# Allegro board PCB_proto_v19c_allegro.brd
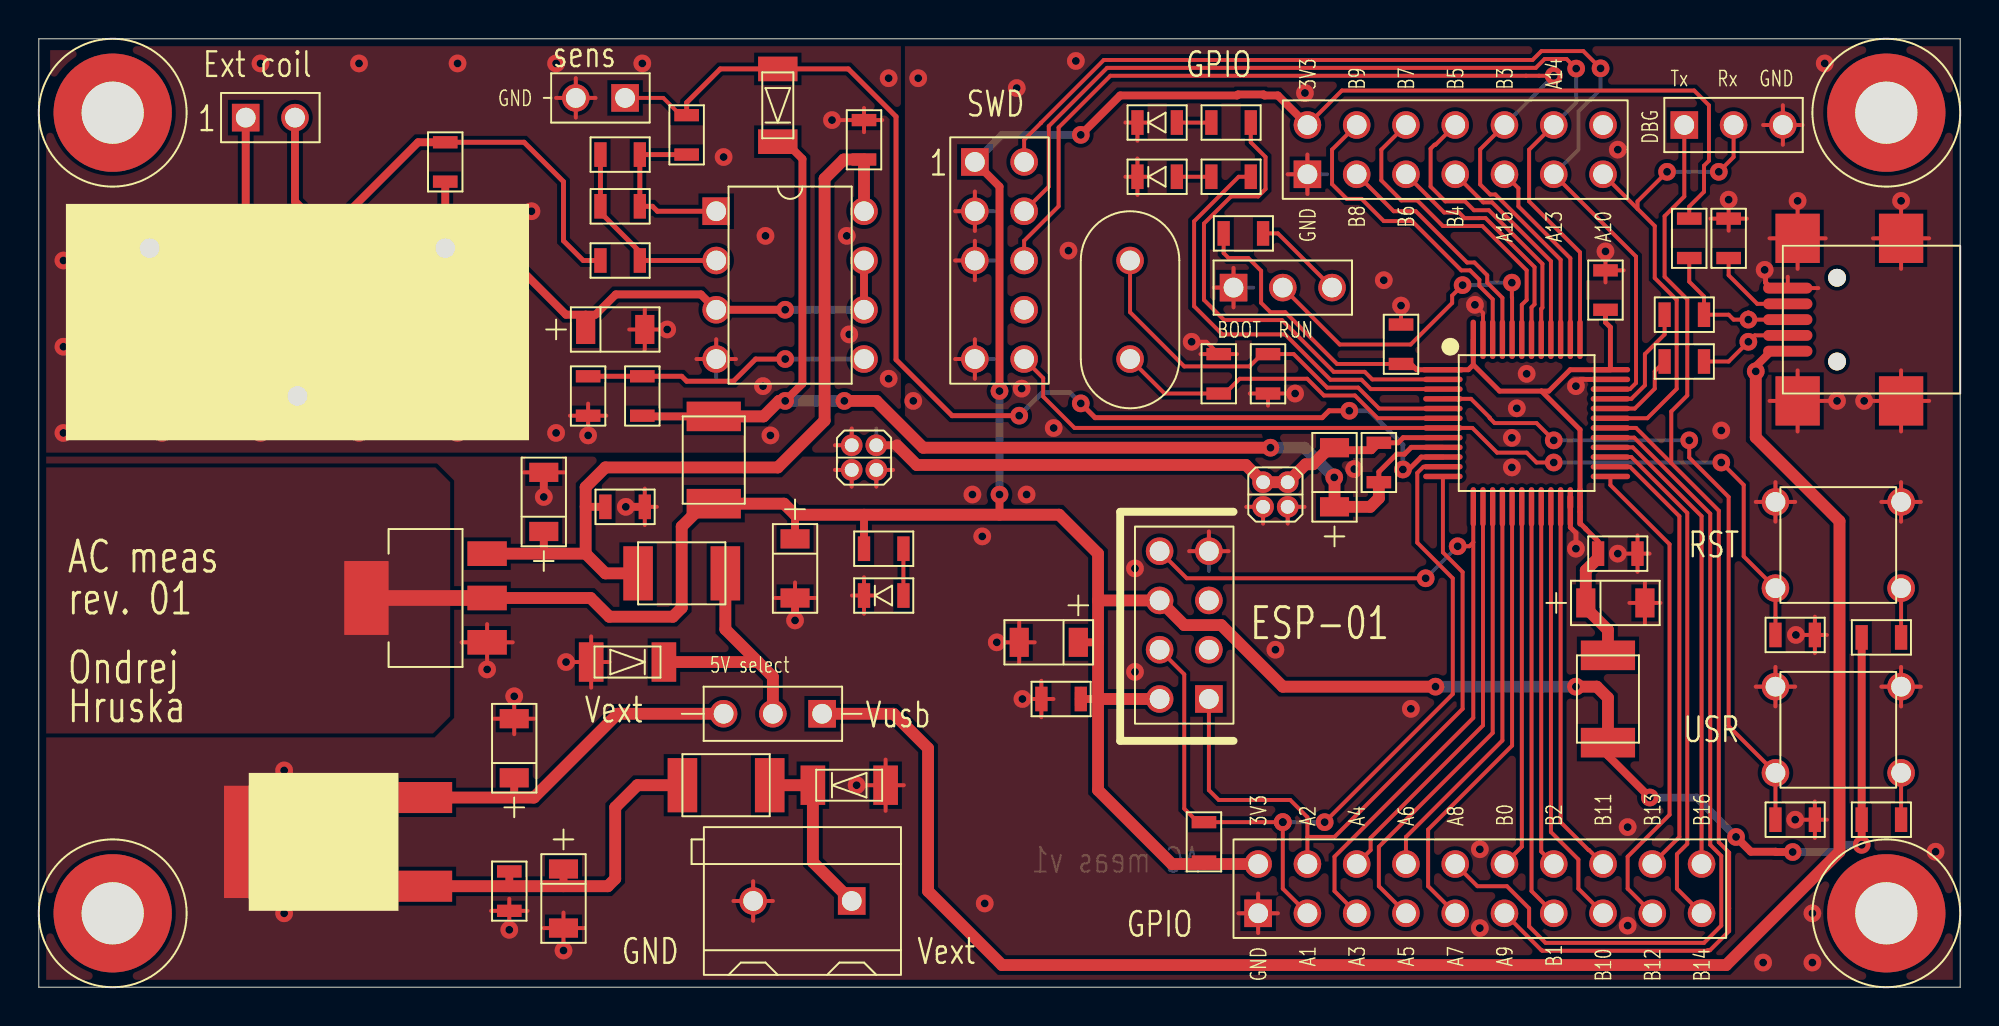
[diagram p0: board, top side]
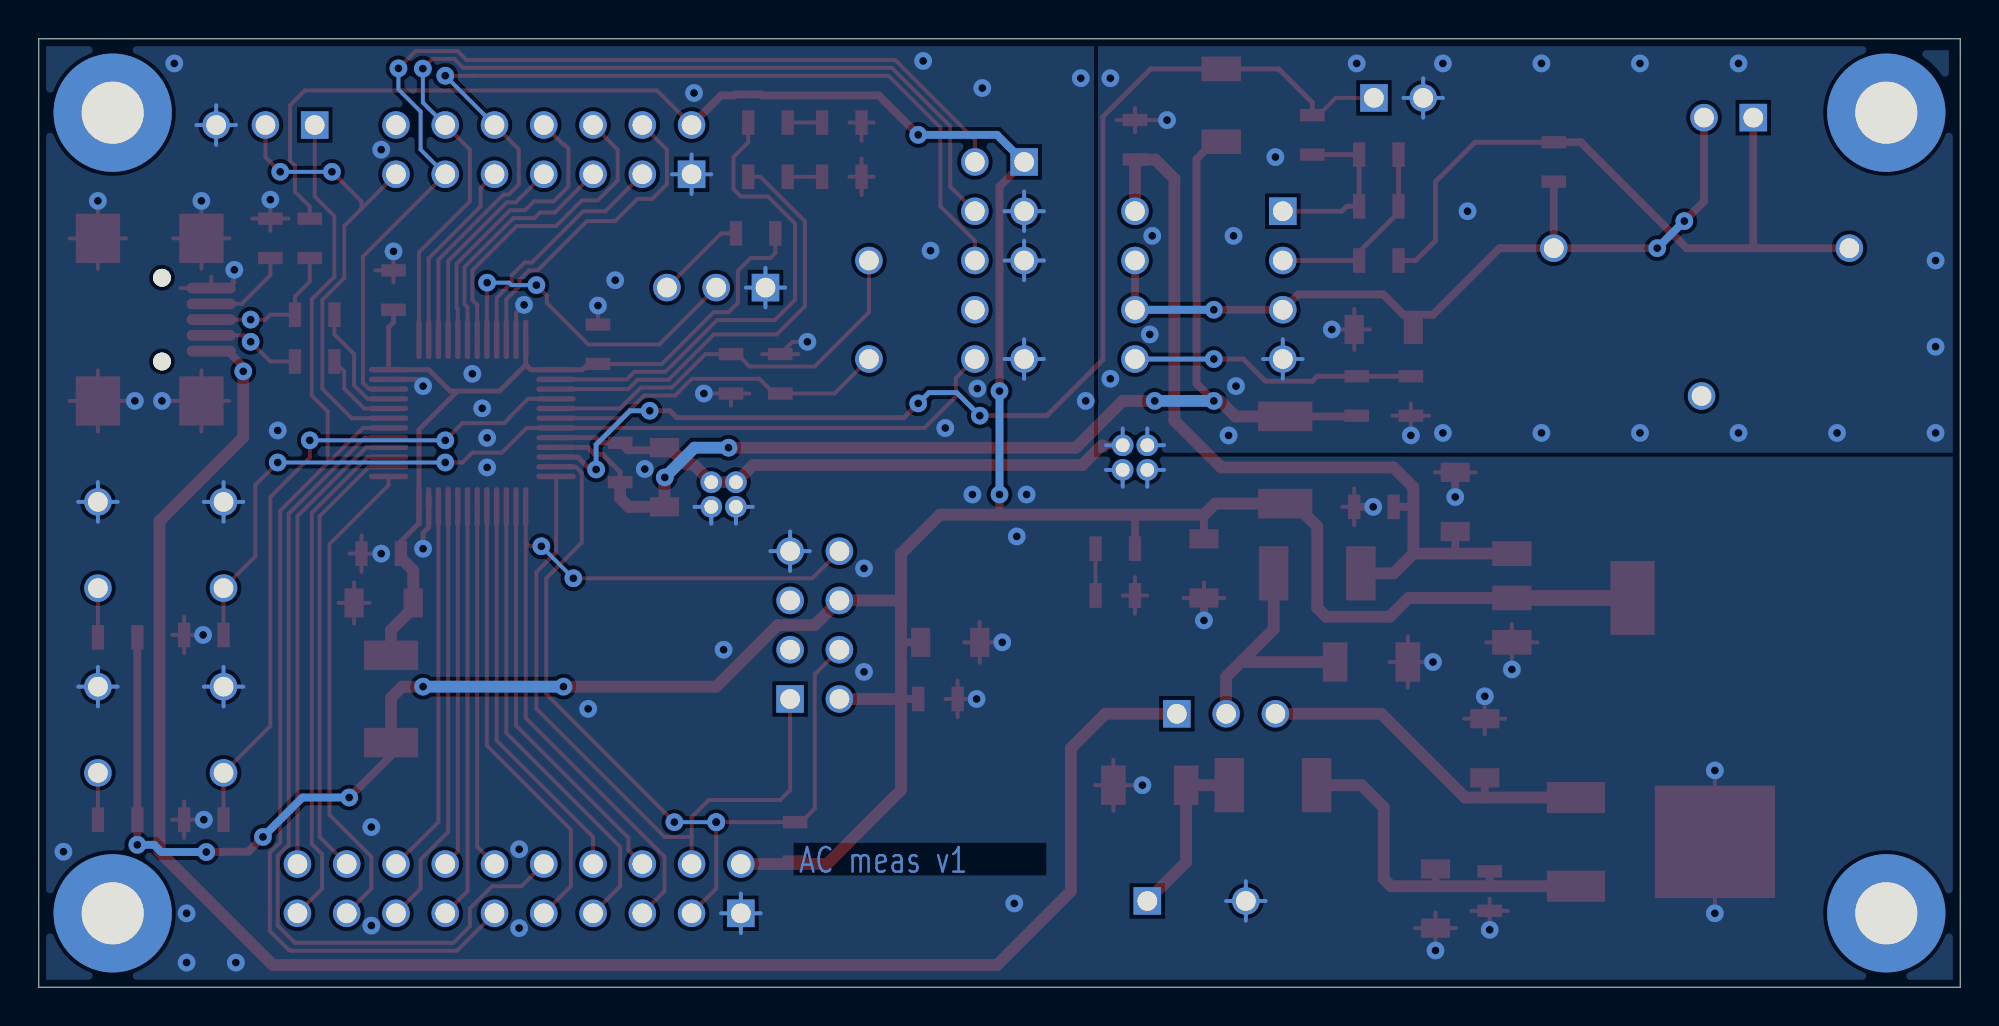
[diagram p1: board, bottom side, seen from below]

Outline 99.06 x 48.9 mm; copper layers: TOP, IN1, IN2, BOTTOM. Coordinates in mm from the lower left corner of the outline.
Outline path: 0,48.9 99.06,48.9 99.06,0 0,0 0,48.9

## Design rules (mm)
net group DP1: nets USB_DM USB_DP

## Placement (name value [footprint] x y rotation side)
C1  10u  [S_1206_CAP]  27.05 4.57 270 top
C2  10u  [S_1206_CAP]  24.51 12.32 90 top
C3  10u  [S_1206_CAP]  26.04 25.02 90 top
C4  100n  [S_0805]  30.23 24.77 0 top
C5  10u  [S_1206_CAP]  38.99 21.59 270 top
C6  1u  [S_1206_CAP]  66.8 26.29 90 top
C7  10n  [S_0805]  69.09 27.05 90 top
C8  10u  [S_1206_CAP]  81.28 19.81 0 top
C9  100n  [S_0805]  80.77 35.94 90 top
C10  100n  [S_0805]  70.23 33.15 90 top
C11  100n  [S_0805]  81.41 22.35 0 top
C12  100n  [S_0805]  90.55 18.16 0 top
C13  100n  [S_0805]  90.55 8.64 0 top
C14  1n5  [S_0805]  29.97 40.26 0 top
C15  10n  [S_0805]  42.55 43.69 90 top
C16  22u  [S_1206_CAP]  29.72 33.91 0 top
C17  22p  [S_0805]  63.37 31.62 270 top
C18  22p  [S_0805]  60.83 31.62 90 top
C19  100n  [S_0805]  24.26 4.95 270 top
C20  100n  [S_0805]  52.7 14.86 180 top
C21  10u  [S_1206_CAP]  52.07 17.78 180 top
D1  BAT42  [S_MINIMELF]  41.78 10.41 0 top
D2  BAT42  [S_MINIMELF]  30.35 16.76 180 top
D3  BAT42  [S_MINIMELF]  38.1 45.47 90 top
H1  MOUNT HOLE M3  [MOUNT_HOLE_M3]  3.81 45.09 0 top
H2  MOUNT HOLE M3  [MOUNT_HOLE_M3]  95.25 45.09 0 top
H3  MOUNT HOLE M3  [MOUNT_HOLE_M3]  95.25 3.81 0 top
H4  MOUNT HOLE M3  [MOUNT_HOLE_M3]  3.81 3.81 0 top
J1  V_EXT  [T_POWER_CON]  39.37 4.45 180 top
J2  PWR_SELECT  [T_SIP3]  37.85 14.1 270 top
J3  EXT_COIL  [T_SIP2]  10.67 44.83 90 top
J4  USB  [S_USB_MINI_B]  92.71 34.42 90 top
J6  SWD 5x2  [T_HEADER_SWD]  49.53 37.47 0 top
J7  GPIO1  [T_HEADER10X2]  74.3 5.08 90 top
J8  HEADER 7X2  [T_HEADER7X2]  73.03 43.18 90 top
J9  TEST_ANALOG_IN  [T_SIP2]  30.23 45.85 270 top
J10  DEBUG  [T_SIP3]  87.38 44.45 90 top
J11  ESP8266  [T_HEADER4X2]  59.05 18.67 180 top
J12  BOOT  [T_SIP3]  64.14 36.07 90 top
L1  27uH  [S_1210]  35.43 10.41 180 top
L2  27uH  [S_1210]  33.15 21.34 180 top
L3  27uH  [S_1210]  34.8 27.18 90 top
L4  27uH  [S_1210]  80.9 14.86 90 top
LD1  D1  [S_0805_LED]  57.66 44.58 0 top
LD2  D2  [S_0805_LED]  57.66 41.78 0 top
LD3  POWER  [S_0805_LED]  43.56 20.19 0 top
NOREF  -  []  99.06 0 90 top
NOREF#2  -  []  0 48.9 0 top
R1  100k  [S_0805]  95 18.03 0 top
R2  100k  [S_0805]  95 8.64 0 top
R3  150  [S_0805]  61.47 44.58 180 top
R4  150  [S_0805]  61.47 41.78 180 top
R5  150  [S_0805]  43.56 22.61 0 top
R6  1K  [S_0805]  20.95 42.55 270 top
R7  10k  [S_0805]  29.97 37.47 0 top
R8  20k  [S_0805]  29.97 42.93 0 top
R9  470R  [S_0805]  33.4 43.94 90 top
R10  1K  [S_0805]  31.11 30.48 90 top
R11  1K  [S_0805]  28.32 30.48 270 top
R12  1K  [S_0805]  85.09 38.61 90 top
R13  22  [S_0805]  84.84 32.26 180 top
R14  22  [S_0805]  84.84 34.67 180 top
R15  100k  [S_0805]  87.12 38.61 90 top
R18  10k  [S_0805]  62.1 38.86 180 top
R19  10k  [S_0805]  60.07 7.49 270 top
SB1  AGND BRIDGE  [T_AGND_BRIDGE]  42.55 27.3 270 top
SB2  AGND BRIDGE  [T_AGND_BRIDGE]  63.75 25.4 270 top
SW1  RESET  [T_BUTTON_KSM]  92.84 22.86 0 top
SW2  USER  [T_BUTTON_KSM]  92.84 13.34 0 top
TR1  AC-1010  [T_TALEMA_CUR_TR]  13.34 34.29 0 top
U1  LF50CDT-TR  [S_DPAK]  19.81 7.49 180 top
U2  LD1117AS33TR  [S_SOT223]  23.11 20.07 180 top
U3  OP213  [T_DIP8]  38.73 36.2 0 top
U4  STM32F303CC  [S_LQFP48]  76.71 29.08 0 top
X1  8MHz  [T_XTAL50]  56.26 34.92 270 top

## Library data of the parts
C1-C3 C5 C6 C8 C16 C21 = CAP POL
C4 C7 C9-C15 C17-C20 = CAPACITOR NON-POL
D1-D3 = DIODE
H1-H4 = MOUNT HOLE M3
J1 J3 J9 = HEADER 2
J2 J10 J12 = JUMPER 3
J4 = USB MINI
J6 = SWD 5x2
J7 = HEADER 10X2
J8 = HEADER 7X2
J11 = HEADER 4X2
L1-L4 = INDUCTOR
LD1-LD3 = LED
R1-R15 R18 R19 = RESISTOR
SB1 SB2 = AGND BRIDGE
SW1 SW2 = SW PUSHBUTTON-SPST-2
TR1 = ac-1010
U1 = LF50CDT-TR
U2 = LD1117AS33TR
U3 = OP213
U4 = stm32f303cct6
X1 = CRYSTAL

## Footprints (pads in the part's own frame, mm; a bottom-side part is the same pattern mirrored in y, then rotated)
MOUNT_HOLE_M3
  round 6.096 hole 3.2: 1(0,0)
S_0805
  rect 0.635x1.27 smd: 1(-1.016,0) 2(1.016,0)
S_0805_LED
  rect 0.635x1.27 smd: 1(-1.016,0) 2(1.016,0)
S_1206_CAP
  rect 0.991x1.499 smd: 1(-1.524,0) 2(1.524,0)
S_1210
  rect 1.524x2.794 smd: 1(-2.25,0) 2(2.25,0)
S_DPAK
  rect 2.997x1.6 smd: 1(0,2.286) 2(0,-2.286)
  rect 6.198x5.791 smd: 3(7.163,0)
S_LQFP48
  rect 2.032x0.279 smd: 1(-4.318,2.752)
  oval 2.032x0.279 smd: 2(-4.318,2.252) 3(-4.318,1.751) 4(-4.318,1.251) 5(-4.318,0.751) 6(-4.318,0.25) 7(-4.318,-0.25) 8(-4.318,-0.751) 9(-4.318,-1.251) 10(-4.318,-1.751) 11(-4.318,-2.252) 12(-4.318,-2.752) 25(4.318,-2.752) 26(4.318,-2.252) 27(4.318,-1.751) 28(4.318,-1.251) 29(4.318,-0.751) 30(4.318,-0.25) 31(4.318,0.25) 32(4.318,0.751) 33(4.318,1.251) 34(4.318,1.751) 35(4.318,2.252) 36(4.318,2.752)
  oval 0.279x2.032 smd: 13(-2.752,-4.318) 14(-2.252,-4.318) 15(-1.751,-4.318) 16(-1.251,-4.318) 17(-0.751,-4.318) 18(-0.25,-4.318) 19(0.25,-4.318) 20(0.751,-4.318) 21(1.251,-4.318) 22(1.751,-4.318) 23(2.252,-4.318) 24(2.752,-4.318) 37(2.752,4.318) 38(2.252,4.318) 39(1.751,4.318) 40(1.251,4.318) 41(0.751,4.318) 42(0.25,4.318) 43(-0.25,4.318) 44(-0.751,4.318) 45(-1.251,4.318) 46(-1.751,4.318) 47(-2.252,4.318) 48(-2.752,4.318)
S_MINIMELF
  rect 1.27x2.032 smd: 1(-1.875,0) 2(1.875,0)
S_SOT223
  rect 2.032x1.27 smd: 1(0,2.286) 2(0,0) 3(0,-2.286)
  rect 2.286x3.81 smd: 4(6.223,0)
S_USB_MINI_B
  round 0.914 hole 0.914: (-2.159,0) (2.159,0)
  oval 0.559x2.54 smd: 1(-1.626,2.54) 2(-0.813,2.54) 3(0,2.54) 4(0.813,2.54) 5(1.626,2.54)
  rect 2.54x2.286 smd: X1(-4.191,2.032) X2(4.191,2.032) X3(-4.191,-3.302) X4(4.191,-3.302)
T_AGND_BRIDGE
  round 1.118 hole 0.711: 1(-0.635,0.635) 2(0.635,0.635) 3(-0.635,-0.635) 4(0.635,-0.635)
T_BUTTON_KSM
  round 1.422 hole 1.016: 1(-3.302,2.159) 2(3.175,2.159) 3(3.175,-2.286) 4(-3.302,-2.286)
T_DIP8
  rect 1.422x1.422 hole 1.016: 1(-3.81,3.81)
  round 1.422 hole 1.016: 2(-3.81,1.27) 3(-3.81,-1.27) 4(-3.81,-3.81) 5(3.81,-3.81) 6(3.81,-1.27) 7(3.81,1.27) 8(3.81,3.81)
T_HEADER4X2
  rect 1.422x1.422 hole 1.016: 1(-1.27,3.81)
  round 1.422 hole 1.016: 2(1.27,3.81) 3(-1.27,1.27) 4(1.27,1.27) 5(-1.27,-1.27) 6(1.27,-1.27) 7(-1.27,-3.81) 8(1.27,-3.81)
T_HEADER7X2
  rect 1.422x1.422 hole 1.016: 1(-1.27,7.62)
  round 1.422 hole 1.016: 2(1.27,7.62) 3(-1.27,5.08) 4(1.27,5.08) 5(-1.27,2.54) 6(1.27,2.54) 7(-1.27,0) 8(1.27,0) 9(-1.27,-2.54) 10(1.27,-2.54) 11(-1.27,-5.08) 12(1.27,-5.08) 13(-1.27,-7.62) 14(1.27,-7.62)
T_HEADER10X2
  rect 1.422x1.422 hole 1.016: 1(-1.27,11.43)
  round 1.422 hole 1.016: 2(1.27,11.43) 3(-1.27,8.89) 4(1.27,8.89) 5(-1.27,6.35) 6(1.27,6.35) 7(-1.27,3.81) 8(1.27,3.81) 9(-1.27,1.27) 10(1.27,1.27) 11(-1.27,-1.27) 12(1.27,-1.27) 13(-1.27,-3.81) 14(1.27,-3.81) 15(-1.27,-6.35) 16(1.27,-6.35) 17(-1.27,-8.89) 18(1.27,-8.89) 19(-1.27,-11.43) 20(1.27,-11.43)
T_HEADER_SWD
  rect 1.422x1.422 hole 1.016: 1(-1.27,5.08)
  round 1.422 hole 1.016: 2(1.27,5.08) 3(-1.27,2.54) 4(1.27,2.54) 5(-1.27,0) 6(1.27,0) 8(1.27,-2.54) 9(-1.27,-5.08) 10(1.27,-5.08)
T_POWER_CON
  rect 1.422x1.422 hole 1.016: 1(-2.54,0)
  round 1.422 hole 1.016: 2(2.54,0)
T_SIP2
  rect 1.422x1.422 hole 1.016: 1(0,0)
  round 1.422 hole 1.016: 2(0,-2.54)
T_SIP3
  rect 1.422x1.422 hole 1.016: 1(0,2.54)
  round 1.422 hole 1.016: 2(0,0) 3(0,-2.54)
T_TALEMA_CUR_TR
  round 1.422 hole 1.016: 1(-7.62,3.81) 2(7.62,3.81) X1(0,-3.81)
T_XTAL50
  round 1.422 hole 1.016: 1(-2.54,0) 2(2.54,0)

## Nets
3V3: C5.1 C20.1 C21.1 J6.1(VCC) J7.2 J8.2 J11.2 J11.6 L3.1 L4.1 R1.1 R2.1 R5.1 R12.2 R19.2 U2.2(VOUT) U2.4(TAB_VOUT)
3V3_ANALOG: C6.1 C7.1 D3.1(K) L3.2 R10.1 U4.9(VDDA)
3V3_MCU: C8.1 C9.1 C10.1 C11.1 L4.2 R18.2 U4.1(VBAT) U4.24(VDD#24) U4.36(VDD#36) U4.48(VDD#48)
5V: C3.1 C4.1 C15.1 L2.2 U2.3(VIN) U3.8(VCC)
5V_REG_OUT: C2.1 J2.3(P3) U1.2(VOUT)
5V_USB: J2.1(P1) J4.1(VBUS)
GND: C1.2 C2.2 C3.2 C4.2 C5.2 C8.2 C9.2 C10.2 C11.2 C12.2 C13.2 C17.2 C18.2 C19.2 C20.2 C21.2 D1.2(A) D2.2(A) J1.2 J4.5(GND) J4.X1 J4.X2 J4.X3 J4.X4 J6.3(GND1) J6.5(GND2) J6.9(GNDD) J7.1 J8.1 J10.3(P3) J11.7 J12.1(P1) LD1.1(CATHODE) LD2.1(CATHODE) LD3.1(CATHODE) R15.2 SB1.2(B1) SB1.4(B2) SB2.2(B1) SB2.4(B2) SW1.1 SW1.2 SW2.1 SW2.2 U1.3(GND) U2.1(GND) U4.23(VSS#23) U4.35(VSS#35) U4.47(VSS#47)
GNDA: C6.2 C7.2 C15.2 C16.2 J9.2 R11.2 SB1.1(A1) SB1.3(A2) SB2.1(A1) SB2.3(A2) U3.4(GND) U4.8(VSSA)
ADC_IN: D3.2(A) J9.1 R9.2 U4.10(PA0)
ESP_NRST: J7.3 J11.4 R19.1 U4.11(PA1)
ESP_RX: J7.4 J11.1 U4.12(PA2)
ESP_TX: J7.5 J11.8 U4.13(PA3)
LED1: R3.1 U4.2(PC13)
LED2: R4.1 U4.3(PC14/OSC32_IN)
NRST: C12.1 J6.10(NRST) SW1.4 U4.7(NRST)
PA4: J7.6 U4.14(PA4)
PA5: J7.7 U4.15(PA5)
PA6: J7.8 U4.16(PA6)
PA7: J7.9 U4.17(PA7)
PA8: J7.10 U4.29(PA8)
PA9: J7.11 J10.1(P1) U4.30(PA9)
PA10: J8.13 J10.2(P2) U4.31(PA10)
PA13: J6.2(SWDIO) J8.11 U4.34(PA13)
PA14: J6.4(SWCLK) J8.12 U4.37(PA14)
PA15: J8.9 U4.38(PA15)
PB0: J7.12 U4.18(PB0)
PB1: J7.13 U4.19(PB1)
PB2: J7.14 U4.20(PB2)
PB3: J6.6(SWO) J8.10 U4.39(PB3)
PB4: J8.7 U4.40(PB4)
PB5: J8.8 U4.41(PB5)
PB6: J8.5 U4.42(PB6)
PB7: J8.6 U4.43(PB7)
PB8: J8.3 U4.45(PB8)
PB9: J8.4 U4.46(PB9)
PB10: J7.15 U4.21(PB10)
PB11: J7.16 U4.22(PB11)
PB12: J7.17 U4.25(PB12)
PB13: J7.18 U4.26(PB13)
PB14: J7.19 U4.27(PB14)
PB15: J7.20 U4.28(PB15)
USB_DM: R13.2 U4.32(PA11)
USB_DP: R14.2 U4.33(PA12)
USER_BTN: C13.1 SW2.4 U4.4(PC15/OSC32_OUT)
N020780: J12.3(P3) R18.1
N31498: J4.3(D+) R12.1 R14.1
N31517: J4.2(D-) R13.1
N33713: C17.1 U4.5(PF0/OSC_IN) X1.1
N33722: C18.1 U4.6(PF1/OSC_OUT) X1.2
N47255: J3.1 R6.1 R7.1 TR1.1
N47331: C14.1 R7.2 R8.1 U3.2(-IN)
N47339: C14.2 R8.2 R9.1 U3.1(OUT)
N47545: C16.1 J3.2 R6.2 TR1.2 U3.3(+IN) U3.6(-IN) U3.7(OUT)
N50175: C1.1 C19.1 L1.2 U1.1(VIN)
N50285: D2.1(K) J2.2(P2) L2.1
N51670: D1.1(K) J1.1 L1.1
N101209: R10.2 R11.1 U3.5(+IN)
N111212: J4.4(ID) R15.1
N127573: J12.2(P2) U4.44(BOOT0)
N648841: R2.2 SW2.3
N650540: LD1.2(ANODE) R3.2
N652140: LD2.2(ANODE) R4.2
N653160: LD3.2(ANODE) R5.2
N656901: R1.2 SW1.3

Pads without a net: H1 1; H2 1; H3 1; H4 1; J6 8; J8 14; J11 3 5; TR1 X1

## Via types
v1: diameter 0.914, hole 0.406, TOP to BOTTOM, 127 vias

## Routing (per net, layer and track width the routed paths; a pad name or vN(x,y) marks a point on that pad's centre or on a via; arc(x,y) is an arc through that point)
3V3: length 198.2
  TOP w0.203: 60.07,6.35 R19.2 ; R12.2 85.09,40.25 85.85,41.01 85.85,42.35 86.11,42.61 86.11,45.47 85.34,46.23 67.18,46.23 J8.2
  TOP w0.406: v1(53.72,43.94) 55.75,45.97 61.78,45.97 61.83,46.02 63.14,46.02 63.19,45.97 63.88,45.97 J8.2 ; v1(83.06,9.78) 80.9,11.94 L4.1 ; v1(49.53,30.73) 49.53,41.27 J6.1 ; v1(93.98,7.34) R2.1 R1.1 ; 49.53,24.36 v1(49.53,25.4) ; C21.1 54.61,17.78 ; 54.61,14.86 C20.1 ; 38.99,24.36 C5.1 ; v1(90.42,6.97) 89.56,6.97 89.54,6.99 88.27,6.99 v1(87.5,7.75) ; 42.55,24.36 R5.1
  TOP w0.61: 54.61,14.86 54.61,10.16 58.42,6.35 J7.2 ; 54.61,14.86 54.61,19.94 ; 54.61,14.86 J11.2 ; 54.61,19.94 54.61,22.35 52.6,24.36 38.99,24.36 38.42,24.93 L3.1 34.33,24.93 33.15,23.75 33.15,19.56 32.69,19.1 29.41,19.1 28.45,20.07 U2.2 ; 54.61,19.94 J11.6 59.05,18.67 60.96,18.67 64.14,15.49 v1(72.01,15.49) ; 53.72,14.54 C20.1 53.72,15.18 ; L4.1 80.9,14.92 80.33,15.49 v1(79.25,15.49)
  TOP w0.813: U2.2 U2.4
  BOTTOM w0.406: v1(87.5,7.75) 85.47,9.78 v1(83.06,9.78) ; v1(93.98,7.34) 93.12,7.34 92.75,6.97 v1(90.42,6.97) ; v1(49.53,25.4) v1(49.53,30.73) ; v1(53.72,43.94) 49.66,43.94 J6.1
  BOTTOM w0.61: v1(79.25,15.49) v1(72.01,15.49)
3V3_ANALOG: length 61.3
  TOP w0.254: 69.09,26.04 69.09,26.57 70,27.48 70.41,27.48 70.76,27.83 U4.9
  TOP w0.406: D3.1 38.48,43.59 39.37,42.7 39.37,31.11 v1(38.48,30.23) ; R10.1 31.41,29.46 31.44,29.43 L3.2
  TOP w0.61: v1(41.53,30.23) 43.18,30.23 45.59,27.81 v1(63.5,27.81) ; v1(38.48,30.23) 38.16,30.23 37.37,29.43 L3.2 ; 69.09,26.04 69.09,25.21 68.64,24.77 C6.1 66.8,26.27 v1(66.79,26.28)
  BOTTOM w0.61: v1(63.5,27.81) 65.26,27.81 v1(66.79,26.28) ; v1(38.48,30.23) v1(41.53,30.23)
3V3_MCU: length 45.6
  TOP w0.203: R18.2 61.09,37.85 61.34,37.59 62.36,37.59 63.02,36.93 63.02,35.28 63.5,34.8 64.26,34.8 66.93,32.13 C10.1
  TOP w0.254: C10.1 70.74,32.13 70.99,31.88 71,31.88 71.04,31.84 U4.1 73.7,31.84 73.96,32.09 ; 80.77,34.92 80.77,34.28 81.03,34.02 U4.36 78.95,31.84 77.85,30.73 77.47,30.73 ; 80.39,22.35 80.39,22.99 79.76,23.62 79.76,23.63 79.47,23.92 79.47,24.5 79.46,24.51 U4.24 79.46,28.74 77.47,30.73 ; U4.48 73.96,32.09 ; 73.96,32.09 75.31,30.73 77.47,30.73
  TOP w0.61: 80.39,22.35 80.39,22.12 79.76,21.49 C8.1 79.76,19.56 80.9,18.41 L4.2
5V: length 45.1
  TOP w0.406: 26.04,22.35 26.04,23.5 ; 28.19,24.77 C4.1
  TOP w0.61: 28.19,22.35 U2.3 ; 28.19,22.35 29.21,21.34 L2.2 ; 28.19,22.35 28.19,25.78 29.21,26.8 38.1,26.8 40.51,29.21 40.51,41.68 41.5,42.67 C15.1 U3.8
5V_REG_OUT: length 18.3
  TOP w0.406: 24.51,9.78 C2.1
  TOP w0.61: J2.3 29.84,14.1 25.53,9.78 U1.2
5V_USB: length 93.3
  TOP w0.406: v1(88.52,31.75) 88.52,32 89.31,32.79 J4.1
  TOP w0.61: v1(88.52,31.75) 88.52,28.35 92.84,24.03 92.84,6.99 86.99,1.14 49.66,1.14 45.85,4.95 45.85,12.32 44.07,14.1 J2.1
GND: length 238.8
  TOP w0.203: 56.64,43.64 LD1.1 ; LD1.1 56.02,44.58 ; LD1.1 57.26,44.58 ; 62.87,2.79 J7.1 ; J7.1 62.87,4.83 ; J7.1 61.85,3.81 ; J7.1 63.88,3.81 ; D1.2 44.6,10.41 ; D1.2 43.66,9.09 ; D1.2 43.66,11.74 ; D1.2 v1(42.16,10.41) ; 64.39,23.9 SB2.2 65.25,24.77 ; 24.26,3.94 25.2,3.94 ; 24.26,3.94 23.32,3.94 ; 24.26,3.94 v1(24.26,2.96) ; 24.26,3.94 24.26,4.56 ; 47.24,37.47 J6.5 ; J6.5 48.26,36.45 ; J6.5 48.26,38.48 ; C21.2 50.55,18.83 ; C21.2 51.35,17.78 ; C21.2 v1(49.39,17.78) ; C21.2 50.55,16.73 ; J8.1 65.41,42.93 ; J8.1 64.39,41.91 ; J8.1 65.41,40.89 ; SW1.2 97.03,25.02 ; SW1.2 95,25.02 ; SW1.2 96.01,26.04 ; SW1.2 96.01,24 ; C9.2 v1(80.77,37.93) ; C9.2 81.71,36.96 ; C9.2 80.77,36.33 ; 87.12,39 R15.2 ; R15.2 88.06,39.62 ; R15.2 86.18,39.62 ; R15.2 v1(87.12,40.6) ; 26,3.05 C1.2 ; C1.2 27.05,3.85 ; C1.2 28.11,3.05 ; C1.2 v1(27.05,1.89) ; 48.26,32.38 48.26,33.4 ; 48.26,32.38 47.24,32.38 ; 48.26,32.38 48.26,31.37 ; 88.52,25.02 SW1.1 ; SW1.1 89.53,24 ; SW1.1 90.55,25.02 ; SW1.1 89.53,26.04 ; 47.24,40.01 J6.3 ; J6.3 48.26,38.99 ; J6.3 48.26,41.02 ; 96.01,28.65 J4.X3 ; J4.X3 v1(94.11,30.23) ; J4.X3 97.46,30.23 ; J4.X3 96.01,31.8 ; 90.17,36.63 J4.5 91.75,36.04 ; C20.2 v1(50.71,14.86) ; C20.2 52.31,14.86 ; C20.2 51.69,13.92 ; C20.2 51.69,15.8 ; 59.89,32.64 C18.2 ; C18.2 60.2,33.27 v1(59.44,33.27) ; C18.2 61.77,32.64 ; 91.57,7.7 C13.2 ; C13.2 91.57,9.58 ; C13.2 v1(90.55,8.64) ; C13.2 92.19,8.64 ; 94.56,38.61 J4.X4 ; J4.X4 97.46,38.61 ; J4.X4 v1(96.01,40.54) ; J4.X4 96.01,37.03 ; 59.31,22.48 J11.7 ; J11.7 61.34,22.48 ; J11.7 60.33,23.5 ; 89.92,43.43 J10.3 ; J10.3 90.93,44.45 ; J10.3 88.9,44.45 ; J10.3 89.92,45.47 ; C12.2 92.19,18.16 ; C12.2 91.57,17.22 ; C12.2 v1(90.59,18.16) ; C12.2 91.57,19.1 ; v1(92.71,30.23) J4.X1 ; J4.X1 90.68,28.65 ; J4.X1 89.23,30.23 ; J4.X1 90.68,31.8 ; 89.53,14.48 SW2.1 ; SW2.1 88.52,15.49 ; SW2.1 90.55,15.49 ; SW2.1 89.53,16.51 ; C17.2 v1(64.77,30.61) ; C17.2 62.43,30.61 ; C17.2 63.37,29.98 ; C8.2 83.6,19.81 ; C8.2 82,19.81 ; C8.2 82.8,20.87 ; C8.2 82.8,18.76 ; 28.48,15.44 D2.2 ; D2.2 29.42,16.76 ; D2.2 28.48,18.09 ; D2.2 v1(27.18,16.76) ; U4.47 74.46,34.76 v1(74.04,35.18) ; 23.46,13.84 C2.2 ; C2.2 25.57,13.84 ; C2.2 v1(24.51,15) ; C2.2 24.51,13.04 ; SW2.2 96.01,16.51 ; SW2.2 97.03,15.49 ; SW2.2 96.01,14.48 ; SW2.2 95,15.49 ; J1.2 36.83,5.46 ; J1.2 37.85,4.45 ; J1.2 35.81,4.45 ; J1.2 36.83,3.43 ; 82.42,21.41 C11.2 ; C11.2 v1(81.41,22.35) ; C11.2 82.42,23.29 ; C11.2 83.05,22.35 ; v1(12.65,11.18) v1(12.65,3.81) ; LD2.1 56.64,42.72 ; LD2.1 56.64,40.84 ; LD2.1 57.26,41.78 ; LD2.1 56.02,41.78 ; 89.23,38.61 J4.X2 ; J4.X2 v1(90.68,40.54) ; J4.X2 92.13,38.61 ; J4.X2 90.68,37.03 ; C10.2 v1(70.23,35.14) ; 42.55,19.25 LD3.1 ; LD3.1 41.92,20.19 ; LD3.1 43.17,20.19 ; LD3.1 42.55,21.13 ; 61.59,35.05 J12.1 ; J12.1 61.59,37.08 ; J12.1 60.58,36.07 ; C5.2 38.99,20.87 ; C5.2 37.93,20.07 ; C5.2 40.04,20.07 ; 31.24,23.82 C4.2 ; C4.2 31.24,25.71 ; C4.2 31.86,24.77 ; 24.98,26.54 C3.2 27.09,26.54 ; 62.25,24.77 SB2.4 63.12,23.9 ; 44.04,26.67 SB1.2 43.18,25.81 ; 41.05,26.67 SB1.4 41.91,25.81 ; U2.1 23.11,18.72 ; U2.1 24.44,17.78 ; U2.1 21.79,17.78 ; U2.1 v1(23.11,16.38)
  TOP w0.254: U4.23 78.96,23.71 79.25,23.42 v1(79.25,22.61) ; v1(79.25,30.99) 79.25,31.11 79.47,31.33 U4.35 ; v1(88.98,36.98) 89.03,36.93 89.03,36.32 89.31,36.04 J4.5
  TOP w0.305: 78.96,25.27 U4.23
  TOP w0.406: C4.2 v1(30.26,24.77) ; v1(26.04,25.27) C3.2 ; C5.2 v1(38.99,18.91)
  BOTTOM w0.203: SW2.1 90.55,15.49 ; SW2.1 89.53,14.48 ; SW2.1 89.53,16.51 ; SW2.1 88.52,15.49 ; SW2.2 96.01,16.51 ; SW2.2 96.01,14.48 ; SW2.2 95,15.49 ; SW2.2 97.03,15.49 ; 88.9,44.45 J10.3 ; J10.3 89.92,43.43 ; J10.3 89.92,45.47 ; J10.3 90.93,44.45 ; 47.24,40.01 J6.3 ; J6.3 48.26,38.99 ; J6.3 49.28,40.01 ; J6.3 48.26,41.02 ; 35.81,4.45 J1.2 ; J1.2 36.83,3.43 ; J1.2 36.83,5.46 ; J1.2 37.85,4.45 ; 65.25,24.77 SB2.2 64.39,23.9 ; 41.91,25.81 SB1.4 41.05,26.67 ; SW1.2 96.01,26.04 ; SW1.2 97.03,25.02 ; SW1.2 95,25.02 ; SW1.2 96.01,24 ; J12.1 61.59,37.08 ; J12.1 61.59,35.05 ; J12.1 62.61,36.07 ; J12.1 60.58,36.07 ; 48.26,31.37 48.26,32.38 ; 48.26,32.38 48.26,33.4 ; 48.26,32.38 47.24,32.38 ; 48.26,32.38 49.28,32.38 ; J7.1 63.88,3.81 ; J7.1 61.85,3.81 ; J7.1 62.87,4.83 ; J7.1 62.87,2.79 ; 59.31,22.48 J11.7 ; J11.7 60.33,23.5 ; J11.7 61.34,22.48 ; J11.7 60.33,21.46 ; 89.53,24 SW1.1 ; SW1.1 90.55,25.02 ; SW1.1 89.53,26.04 ; SW1.1 88.52,25.02 ; 43.18,25.81 SB1.2 44.04,26.67 ; 64.39,41.91 J8.1 ; J8.1 65.41,42.93 ; J8.1 65.41,40.89 ; J8.1 66.42,41.91 ; 48.26,36.45 J6.5 ; J6.5 47.24,37.47 ; J6.5 48.26,38.48 ; J6.5 49.28,37.47 ; 63.12,23.9 SB2.4 62.25,24.77
  vias: v1(45.09,30.23) v1(45.34,46.86) v1(48.13,25.4) v1(48.64,23.24) v1(48.77,4.32) v1(50.42,46.35) v1(50.67,30.86) v1(50.93,25.4) v1(52.32,28.83) v1(53.09,37.97) v1(53.47,47.75) v1(56.52,21.59) v1(56.52,16.26) v1(63.75,17.4) v1(65.28,46.1) v1(67.82,26.71) v1(69.34,36.45) v1(70.74,14.35) v1(74.3,7.11) v1(74.3,3.05) v1(75.95,28.32) v1(75.95,26.8) v1(76.2,29.84) v1(76.71,31.62) v1(81.41,43.18) v1(81.92,8.26) v1(81.92,3.17) v1(86.74,28.7) v1(88.9,1.27) v1(91.44,3.81) v1(91.44,1.27) v1(92.08,47.62) v1(97.79,6.99)
GNDA: length 62.9
  TOP w0.203: 41.05,27.94 SB1.3 41.91,28.8 ; 31.24,32.85 C16.2 ; C16.2 31.24,34.96 ; C16.2 30.44,33.91 ; C16.2 v1(32.4,33.91) ; C15.2 43.49,44.7 ; C15.2 42.55,44.08 ; C15.2 42.55,45.33 ; C15.2 v1(40.89,44.7) ; R11.2 v1(28.32,28.45) ; R11.2 28.32,30.09 ; R11.2 29.26,29.46 ; R11.2 27.38,29.46 ; U3.4 34.92,33.4 ; U3.4 35.94,32.38 ; U3.4 33.91,32.38 ; J9.2 27.69,46.86 ; J9.2 26.67,45.85 ; J9.2 28.7,45.85 ; J9.2 27.69,44.83
  TOP w0.254: C7.2 70.08,28.07 70.34,28.33 U4.8
  TOP w0.406: C7.2 68.71,27.69 66.93,27.69 66.8,27.81 ; 44.25,27.94 SB1.1
  TOP w0.61: 66.8,27.81 66.55,27.81 65.69,26.96 65.31,26.96 SB2.1 SB2.3 62.23,26.92 45.26,26.92 44.25,27.94
  BOTTOM w0.203: 43.18,28.8 SB1.1 44.04,27.94 ; 41.91,28.8 SB1.3 41.05,27.94 ; U3.4 35.94,32.38 ; U3.4 33.91,32.38 ; U3.4 34.92,33.4 ; U3.4 34.92,31.37 ; 26.67,45.85 J9.2 ; J9.2 28.7,45.85 ; J9.2 27.69,44.83 ; J9.2 27.69,46.86
  vias: v1(1.27,37.47) v1(1.27,33.02) v1(1.27,28.57) v1(6.35,28.57) v1(11.43,47.62) v1(11.43,28.57) v1(16.51,47.62) v1(16.51,28.57) v1(21.59,47.62) v1(21.59,28.57) v1(25.4,40.01) v1(26.67,47.62) v1(26.67,28.57) v1(31.11,47.62) v1(35.31,42.8) v1(37.34,30.99) v1(37.47,38.73) v1(37.72,28.45) v1(41.66,38.73) v1(41.78,33.66) v1(43.81,46.86) v1(43.81,31.37)
ADC_IN: length 62.1
  TOP w0.203: R9.2 33.08,44.96 32.19,45.85 J9.1
  TOP w0.254: v1(50.55,29.46) 47.09,29.46 44.2,32.36 44.2,44.88 41.74,47.34 D3.2 35.14,47.34 33.4,45.61 R9.2 ; v1(67.56,29.72) 66.52,29.72 66.17,29.36 54.46,29.36 v1(53.72,30.1) ; U4.10 71.27,27.33 70.64,26.69 v1(70.33,26.69)
  BOTTOM w0.254: v1(67.56,29.72) 68.58,29.72 70.33,27.97 v1(70.33,26.69) ; v1(53.72,30.1) 53.16,30.66 51.74,30.66 v1(50.55,29.46)
ESP_NRST: length 44.4
  TOP w0.203: J11.4 59.05,16.13 59.05,9.21 59.75,8.51 R19.1 v1(64.14,8.51) 64.14,5.08 J7.3 ; U4.11 71.39,26.83 71.07,26.52 71.07,22.92 72.9,21.08 72.9,15.11 v1(66.29,8.51)
  BOTTOM w0.203: v1(64.14,8.51) v1(66.29,8.51)
ESP_RX: length 35.9
  TOP w0.203: U4.12 72.39,22.42 73.41,21.4 73.41,14.35 66.8,7.75 65.41,7.75 ; 65.41,7.75 J7.4 ; 65.41,7.75 65.41,8.76 64.52,9.65 60.83,9.65 60.33,10.16 J11.1
ESP_TX: length 42.4
  TOP w0.203: J11.8 59.18,21.08 v1(71.5,21.08) ; 73.96,22.94 U4.13 73.96,25.27 ; 73.96,22.94 73.96,13.88 66.8,6.73 66.8,4.95 67.94,3.81 ; 73.96,22.94 73.75,22.73 v1(73.15,22.73)
  BOTTOM w0.203: v1(73.15,22.73) v1(71.5,21.08)
LED1: length 26.1
  TOP w0.203: 72.9,31.33 U4.2 68.75,31.33 68.36,31.72 66.76,31.72 64.09,34.39 61.11,34.39 60.07,35.43 60.07,39.37 61.47,40.77 62.87,40.77 63.25,41.15 63.25,42.8 62.48,43.56 R3.1
LED2: length 23.4
  TOP w0.203: R4.1 61.86,41.78 59.56,39.48 59.56,35.11 61.01,33.66 64.26,33.66 66.59,31.32 68.19,31.32 68.68,30.83 U4.3 72.9,30.83
NRST: length 48.8
  TOP w0.203: C12.1 SW1.4 87.9,22.21 87.9,25.89 v1(86.74,27.05) ; 50.8,32.38 51.78,31.4 51.78,30.45 53.4,28.83 U4.7 73.91,28.83 75.18,27.56 76.71,27.56 77.22,27.05 v1(78.11,27.05)
  BOTTOM w0.203: v1(86.74,27.05) v1(78.11,27.05)
PA4: length 21.6
  TOP w0.203: 67.94,6.35 68.66,7.07 68.66,7.7 74.46,13.5 U4.14 74.46,25.27
PA5: length 24.5
  TOP w0.203: J7.7 69.09,5.21 69.09,7.24 74.96,13.11 U4.15 74.96,25.27
PA6: length 21
  TOP w0.203: J7.8 70.48,7.75 75.46,12.72 U4.16 75.46,25.27
PA7: length 23.8
  TOP w0.203: 75.96,25.27 U4.17 75.96,12.46 71.63,8.13 71.63,5.21 J7.9
PA8: length 44.6
  TOP w0.203: U4.29 82.25,28.33 86.17,24.41 86.17,7.34 86.74,6.77 86.74,3.17 85.85,2.29 77.68,2.29 76.83,3.13 76.83,4.06 75.69,5.21 74.17,5.21 J7.10
PA9: length 60.7
  TOP w0.203: U4.30 82.35,28.83 84.16,27.01 ; 84.16,27.01 86.61,24.57 86.61,7.47 87.15,6.94 87.15,4.06 87.15,2.9 86.16,1.91 86.05,1.91 86.02,1.88 77.52,1.88 77.49,1.91 77.47,1.91 J7.11 ; 84.16,27.01 84.16,29.68 84.99,30.51 84.99,35.46 83.82,36.63 83.82,39.75 84.84,40.77 J10.1
PA10: length 24.6
  TOP w0.203: 82.42,40.13 83.31,39.24 83.31,36.56 84.44,35.43 84.44,30.85 82.93,29.33 U4.31 ; 82.42,40.13 80.64,41.91 ; 82.42,40.13 82.42,40.51 v1(83.95,42.04) ; J10.2 87.38,42.8 v1(86.61,42.04)
  BOTTOM w0.203: v1(86.61,42.04) v1(83.95,42.04)
PA13: length 53.6
  TOP w0.203: J8.11 82.35,37.67 82.35,31.15 82.03,30.83 U4.34 ; J6.2 50.8,43.69 51.66,44.55 51.66,44.56 54.91,47.8 55.24,47.8 55.24,47.8 77.01,47.8 77.47,48.26 79.63,48.26 v1(80.52,47.37)
  BOTTOM w0.203: v1(80.52,47.37) 80.52,46.29 79.38,45.15 79.38,43.18 J8.11
PA14: length 50.3
  TOP w0.203: J6.4 52.07,41.27 52.07,44.39 55.08,47.4 77.18,47.4 77.64,47.85 78.77,47.85 v1(79.26,47.36) ; J8.12 76.83,43.18 76.83,40.51 79.46,37.89 U4.37 79.46,32.89
  BOTTOM w0.203: J8.12 79.26,45.61 v1(79.26,47.36)
PA15: length 10.4
  TOP w0.203: 75.56,41.91 76.28,41.19 76.28,40.26 78.96,37.58 U4.38 78.96,32.89
PB0: length 19.3
  TOP w0.203: J7.12 76.46,7.24 U4.18 76.46,25.27
PB1: length 21.9
  TOP w0.203: 76.96,25.27 U4.19 76.96,4.96 J7.13
PB2: length 19.2
  TOP w0.203: 77.46,25.27 U4.20 77.46,7 J7.14
PB3: length 51.8
  TOP w0.203: J6.6 50.8,38.48 52.58,40.26 52.58,44.32 55.24,46.99 76.67,46.99 77.34,46.99 77.34,46.99 v1(78.11,46.99) ; 75.56,44.45 74.31,43.2 74.31,41.39 74.83,40.87 75.1,40.87 78.46,37.5 U4.39 78.46,32.89
  BOTTOM w0.203: v1(78.11,46.99) 75.56,44.45
PB4: length 11.3
  TOP w0.203: 77.96,32.89 U4.40 77.96,37.43 74.93,40.46 74.47,40.46 J8.7
PB5: length 15.6
  TOP w0.203: J8.8 72.01,43.43 71.96,43.43 71.75,43.23 71.75,41.27 72.52,40.51 73.53,40.51 73.99,40.06 74.76,40.06 77.52,37.29 77.52,35.04 77.46,34.97 U4.41 77.46,32.89
PB6: length 12.9
  TOP w0.203: 76.96,32.89 U4.42 76.96,35.05 77.11,35.2 77.11,37.13 74.59,39.65 74.25,39.65 73.51,39.65 73.22,39.94 72.45,39.94 J8.5
PB7: length 17
  TOP w0.203: 76.46,32.89 U4.43 76.46,35.18 76.71,35.43 76.71,36.96 74.42,39.24 72.39,39.24 71.07,40.56 70.25,40.56 69.22,41.6 69.22,43.18 J8.6
PB8: length 13
  TOP w0.203: 75.46,32.89 U4.45 75.46,35.54 74.68,36.32 74.68,36.7 74.02,37.36 73.63,37.36 70.99,40.01 69.85,40.01 67.94,41.91
PB9: length 17.1
  TOP w0.203: 67.94,44.45 66.67,43.18 66.67,41.4 67.44,40.64 68.2,40.64 69.34,39.5 70.8,39.5 73.34,36.96 73.79,36.96 74.27,36.47 74.27,36.15 74.96,35.47 U4.46 74.96,32.89
PB10: length 22.6
  TOP w0.203: 77.96,25.27 U4.21 77.96,8 79.38,6.58 79.38,5.08 J7.15
PB11: length 19.8
  TOP w0.203: J7.16 79.93,7.07 79.9,7.07 78.46,8.51 U4.22 78.46,25.27
PB12: length 25.2
  TOP w0.203: J7.17 81.92,5.08 81.92,6.73 84.07,8.89 84.07,22.84 81.03,25.89 U4.25
PB13: length 23.1
  TOP w0.203: J7.18 84.58,7.75 84.58,24.28 82.03,26.83 U4.26
PB14: length 26.5
  TOP w0.203: J7.19 84.45,5.08 84.45,6.86 84.99,7.39 84.99,24.45 82.1,27.33 U4.27
PB15: length 24.1
  TOP w0.203: U4.28 82.18,27.83 85.72,24.29 J7.20
USB_DM: length 4.3
  TOP w0.203: U4.32 82.28,29.83 83.31,30.86 83.31,31.75 R13.2
USB_DP: length 6.1
  TOP w0.203: U4.33 82.1,30.33 82.8,31.03 82.8,32.64 83.82,33.66 R14.2
USER_BTN: length 35
  TOP w0.203: C13.1 89.53,11.05 87.12,13.46 87.12,25.27 85.09,27.31 v1(85.09,28.19) ; v1(78.11,28.19) 77.22,29.08 75.06,29.08 74.8,29.34 74.8,29.37 73.84,30.33 U4.4
  BOTTOM w0.203: v1(78.11,28.19) v1(85.09,28.19)
N020780: length 4.7
  TOP w0.203: J12.3 63.88,38.86 R18.1
N31498: length 8
  TOP w0.203: R12.1 85.09,36.37 85.85,35.61 R14.1 87.12,34.67 87.38,34.42 v1(88.14,34.42) ; J4.3 v1(88.14,34.42) ; v1(88.14,34.42) 88.14,34.8
N31517: length 4.9
  TOP w0.203: R13.1 87.12,32.26 v1(88.14,33.27) 88.47,33.6 J4.2
N33713: length 21.9
  TOP w0.203: 72.9,29.83 U4.5 69.1,29.83 68.02,30.91 66.42,30.91 64.7,32.64 C17.1 63.06,32.64 62.42,32 59.05,32 56.26,34.8 X1.1
N33722: length 18.5
  TOP w0.203: X1.2 58.04,30.61 C18.1 61.15,30.61 61.91,31.37 65.39,31.37 66.26,30.51 67.85,30.51 69.03,29.33 U4.6 72.9,29.33
N47255: length 36.5
  TOP w0.254: R7.1 28.07,37.47 27.05,38.48 27.05,41.53 25.02,43.56 R6.1
  TOP w0.406: 10.67,38.1 14.1,38.1 19.56,43.56 R6.1 ; 10.67,38.1 J3.1 ; 10.67,38.1 TR1.1
N47331: length 10.2
  TOP w0.254: R8.1 C14.1 28.96,39.94 30.99,37.91 R7.2 U3.2
N47339: length 9.5
  TOP w0.254: U3.1 31.89,40.01 31.64,40.26 C14.2 R8.2 R9.1
  TOP w0.406: U3.1 35.31,40.01
N47545: length 43.6
  TOP w0.406: J3.2 13.21,40.51 v1(14.22,39.5) ; 28.19,34.67 27.18,34.67 23.75,38.1 TR1.2 ; 28.19,34.67 C16.1 ; 28.19,34.67 28.7,34.67 29.75,35.72 34.13,35.72 U3.3 v1(38.48,34.92) ; v1(15.62,38.1) TR1.2 ; TR1.2 R6.2 ; U3.7 U3.6
  BOTTOM w0.406: v1(38.48,34.92) U3.6 ; v1(15.62,38.1) v1(14.22,39.5)
N50175: length 19.3
  TOP w0.406: 27.05,5.21 C1.1 ; 24.26,5.21 C19.1
  TOP w0.61: U1.1 29.34,5.21 29.72,5.59 29.72,9.27 30.86,10.41 L1.2
N50285: length 13.1
  TOP w0.61: J2.2 37.85,16 37.08,16.76 ; L2.1 35.4,18.45 37.08,16.76 ; 37.08,16.76 D2.1
N51670: length 9
  TOP w0.61: J1.1 39.91,6.45 D1.1 L1.1
N101209: length 14.8
  TOP w0.254: R11.1 R10.2 33.15,31.5 33.4,31.24 35.81,31.24 36.96,32.38 v1(38.48,32.38)
  BOTTOM w0.254: v1(38.48,32.38) U3.5
N111212: length 4.5
  TOP w0.203: J4.4 88.6,35.23 87.12,36.7 R15.1
N127573: length 18
  TOP w0.203: 75.96,32.89 U4.44 75.96,35.55 75.95,35.56 v1(75.95,36.32) ; v1(73.41,36.2) 72.87,35.66 72.87,35.28 70.73,33.13 67.07,33.13 J12.2
  BOTTOM w0.203: v1(75.95,36.32) 74.8,36.32 74.68,36.2 v1(73.41,36.2)
N648841: length 2.4
  TOP w0.203: R2.2 96.01,11.05
N650540: length 1.8
  TOP w0.203: LD1.2 R3.2
N652140: length 1.8
  TOP w0.203: LD2.2 R4.2
N653160: length 2.4
  TOP w0.203: R5.2 LD3.2
N656901: length 2.5
  TOP w0.203: R1.2 SW1.3

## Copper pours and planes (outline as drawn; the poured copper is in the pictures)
3V3 on TOP: 20.32,13.08 21.21,13.97 21.21,26.04 20.45,26.8 0.38,26.8 0.38,13.08
GND on TOP, BOTTOM: 0.38,48.51 0.38,0.38 98.68,0.38 98.68,48.51
GNDA on TOP, BOTTOM: 0.38,48.51 0.38,27.56 44.45,27.56 44.45,48.51 ; 1 cut-out

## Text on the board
BOTTOM: AC meas v1
Ref Des/Silkscreen Top: GND | 5V select | BOOT  RUN | Tx | Rx | 3V3 | A2 | A1 | B9 | B8 | A4 | A3 | B7 | B6 | A6 | A5 | B5 | B4 | A8 | A7 | B3 | A16 | B0 | A9 | A14 | A13 | B2 | B1 | A10 | B11 | B10 | DBG | B13 | B12 | B16 | B14 | 1 | Ext coil | sens | Vext | Vusb | SWD | GPIO | USR | RST | AC meas | rev. 01 | Ondrej | Hruska | ESP-01
